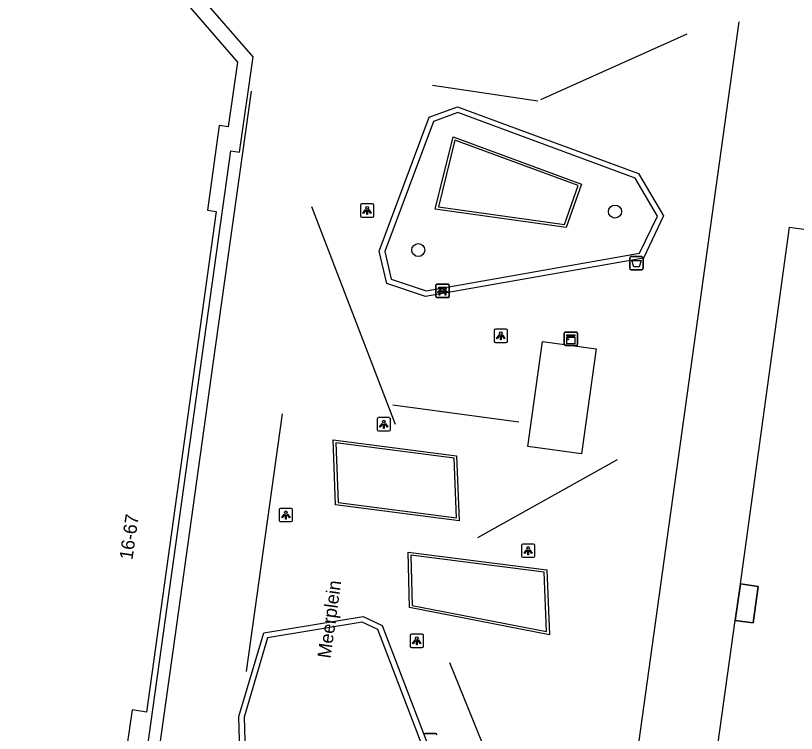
# Model space of a CAD drawing. Extents: x 155640 to 156810, y 382822 to 384046.
# Drawn here: x 156509.5 to 156568, y 383692.6 to 383746.4 of the extents above; entities that cross this region are included whole.
import ezdxf

# ---------------------------------------------------------------- set-up
doc = ezdxf.new("R2010")
doc.units = 0
for name, color, linetype in [('IMGEO_Afvalbak', 7, 'Continuous'), ('IMGEO_Bank', 7, 'Continuous'), ('IMGEO_Boom', 7, 'Continuous'), ('IMGEO_Kast', 7, 'Continuous'), ('IMGEO_Lichtpunt', 7, 'Continuous'), ('IMGEO_Lijnafwatering', 7, 'Continuous'), ('IMGEO_Muur', 7, 'Continuous'), ('IMGEO_Openbare_ruimte_label', 7, 'Continuous'), ('IMGEO_Pand', 7, 'Continuous'), ('IMGEO_Pand_nummerreeks', 7, 'Continuous'), ('IMGEO_Pand_overbouw', 7, 'Continuous'), ('IMGEO_Voetgangersgebied_open', 7, 'Continuous'), ('IMGEO_Voetpad_open', 7, 'Continuous')]:
    doc.layers.add(name, color=color, linetype=linetype)

msp = doc.modelspace()

# ---------------------------------------------------------------- linework, layer by layer
at = {"layer": 'IMGEO_Afvalbak'}
for p, q in [((156555.544, 383727.432), (156555.544, 383728.232)), ((156555.544, 383728.232), (156555.544, 383727.432)), ((156555.644, 383728.332), (156556.434, 383728.332)), ((156556.434, 383728.332), (156555.644, 383728.332)), ((156556.534, 383728.232), (156556.534, 383727.432)), ((156556.534, 383727.432), (156556.534, 383728.232)), ((156556.434, 383727.332), (156555.644, 383727.332)), ((156555.644, 383727.332), (156556.434, 383727.332)), ((156540.197, 383692.575), (156540.987, 383692.575)), ((156540.987, 383692.575), (156540.197, 383692.575))]:
    msp.add_line(p, q, dxfattribs=at)
msp.add_lwpolyline([(156555.687, 383728.046), (156556.391, 383728.046), (156556.242, 383727.576), (156555.836, 383727.576), (156555.687, 383728.046)], dxfattribs=at)
for centre, start, end in [((156555.644, 383728.232), 90, 180), ((156555.644, 383728.232), 90, 180), ((156556.434, 383728.232), 0, 90), ((156556.434, 383728.232), 360, 90), ((156555.644, 383727.432), 180, 270), ((156555.644, 383727.432), 180, 270), ((156556.434, 383727.432), 270, 0), ((156556.434, 383727.432), 270, 0), ((156540.197, 383692.475), 90, 180), ((156540.197, 383692.475), 90, 180), ((156540.987, 383692.475), 0, 90), ((156540.987, 383692.475), 360, 90)]:
    msp.add_arc(centre, 0.1, start, end, dxfattribs=at)
at = {"layer": 'IMGEO_Bank'}
for p, q in [((156541.005, 383725.339), (156541.005, 383726.18)), ((156541.005, 383726.18), (156541.005, 383725.339)), ((156541.08, 383726.264), (156541.921, 383726.264)), ((156541.921, 383726.264), (156541.08, 383726.264)), ((156541.314, 383725.77), (156541.314, 383725.876)), ((156541.358, 383725.876), (156541.358, 383725.77)), ((156541.646, 383725.882), (156541.364, 383725.882)), ((156541.652, 383725.77), (156541.652, 383725.876)), ((156541.696, 383725.876), (156541.696, 383725.77)), ((156542.005, 383726.189), (156542.005, 383725.348)), ((156542.005, 383725.348), (156542.005, 383726.189)), ((156541.93, 383725.264), (156541.089, 383725.264)), ((156541.089, 383725.264), (156541.93, 383725.264)), ((156541.702, 383725.662), (156541.309, 383725.662)), ((156541.364, 383725.764), (156541.646, 383725.764))]:
    msp.add_line(p, q, dxfattribs=at)
for points in [[(156541.308, 383725.882), (156541.222, 383725.882), (156541.222, 383726.043), (156541.785, 383726.043), (156541.785, 383725.882), (156541.702, 383725.882)], [(156541.252, 383725.662), (156541.11, 383725.662), (156541.222, 383725.764), (156541.308, 383725.764)], [(156541.302, 383725.655), (156541.302, 383725.448), (156541.259, 383725.448), (156541.259, 383725.655)], [(156541.702, 383725.764), (156541.785, 383725.764), (156541.897, 383725.662), (156541.758, 383725.662)], [(156541.752, 383725.655), (156541.752, 383725.448), (156541.708, 383725.448), (156541.708, 383725.655)]]:
    msp.add_lwpolyline(points, dxfattribs=at)
for centre, radius, start, end in [((156541.083, 383726.186), 0.0779, 92.4484, 184.28452), ((156541.083, 383726.186), 0.0779, 92.4484, 184.28452), ((156541.307, 383725.875), 0.00671, 2.89567, 87.10433), ((156541.364, 383725.875), 0.00671, 92.89567, 177.10433), ((156541.646, 383725.875), 0.00671, 2.89567, 87.10433), ((156541.703, 383725.875), 0.00671, 92.89567, 177.10433), ((156541.927, 383726.186), 0.0779, 2.4484, 94.28452), ((156541.927, 383726.186), 0.0779, 2.4484, 94.28452), ((156541.083, 383725.342), 0.0779, 182.4484, 274.28452), ((156541.083, 383725.342), 0.0779, 182.4484, 274.28452), ((156541.252, 383725.655), 0.00671, 2.89567, 87.10433), ((156541.309, 383725.655), 0.00671, 92.89567, 177.10433), ((156541.307, 383725.771), 0.00671, 272.89567, 357.10433), ((156541.364, 383725.771), 0.00671, 182.89567, 267.10433), ((156541.646, 383725.771), 0.00671, 272.89567, 357.10433), ((156541.703, 383725.771), 0.00671, 182.89567, 267.10433), ((156541.701, 383725.655), 0.00671, 2.89567, 87.10433), ((156541.758, 383725.655), 0.00671, 92.89567, 177.10433), ((156541.927, 383725.342), 0.0779, 272.4484, 4.28452), ((156541.927, 383725.342), 0.0779, 272.4484, 4.28452)]:
    msp.add_arc(centre, radius, start, end, dxfattribs=at)
at = {"layer": 'IMGEO_Boom'}
for centre in [(156554.432, 383731.713), (156539.683, 383728.825)]:
    msp.add_circle(centre, 0.489, dxfattribs=at)
at = {"layer": 'IMGEO_Kast'}
for p, q in [((156550.631, 383721.746), (156550.631, 383722.587)), ((156550.631, 383722.587), (156550.631, 383721.746)), ((156550.706, 383722.671), (156551.547, 383722.671)), ((156551.547, 383722.671), (156550.706, 383722.671)), ((156551.631, 383722.596), (156551.631, 383721.755)), ((156551.631, 383721.755), (156551.631, 383722.596)), ((156551.556, 383721.671), (156550.715, 383721.671)), ((156550.715, 383721.671), (156551.556, 383721.671))]:
    msp.add_line(p, q, dxfattribs=at)
for points in [[(156550.826, 383722.461), (156551.426, 383722.461), (156551.426, 383722.376), (156550.826, 383722.376), (156550.826, 383722.461)], [(156550.826, 383722.286), (156551.426, 383722.286), (156551.426, 383721.797), (156550.826, 383721.797), (156550.826, 383722.286)]]:
    msp.add_lwpolyline(points, dxfattribs=at)
msp.add_circle((156550.91, 383722.135), 0.0377, dxfattribs=at)
for centre, start, end in [((156550.709, 383722.593), 92.4484, 184.28452), ((156550.709, 383722.593), 92.4484, 184.28452), ((156551.553, 383722.593), 2.4484, 94.28452), ((156551.553, 383722.593), 2.4484, 94.28452), ((156550.709, 383721.749), 182.4484, 274.28452), ((156550.709, 383721.749), 182.4484, 274.28452), ((156551.553, 383721.749), 272.4484, 4.28452), ((156551.553, 383721.749), 272.4484, 4.28452)]:
    msp.add_arc(centre, 0.0779, start, end, dxfattribs=at)
at = {"layer": 'IMGEO_Lichtpunt'}
for p, q in [((156536.245, 383732.286), (156535.437, 383732.286)), ((156536.245, 383732.286), (156535.437, 383732.286)), ((156535.343, 383732.191), (156535.343, 383731.384)), ((156535.343, 383732.191), (156535.343, 383731.384)), ((156536.339, 383731.384), (156536.339, 383732.191)), ((156536.339, 383731.384), (156536.339, 383732.191)), ((156535.437, 383731.29), (156536.245, 383731.29)), ((156535.437, 383731.29), (156536.245, 383731.29)), ((156546.272, 383722.89), (156545.464, 383722.89)), ((156546.272, 383722.89), (156545.464, 383722.89)), ((156545.37, 383722.795), (156545.37, 383721.988)), ((156545.37, 383722.795), (156545.37, 383721.988)), ((156546.366, 383721.988), (156546.366, 383722.795)), ((156546.366, 383721.988), (156546.366, 383722.795)), ((156545.464, 383721.894), (156546.272, 383721.894)), ((156545.464, 383721.894), (156546.272, 383721.894)), ((156536.593, 383716.159), (156536.593, 383715.352)), ((156536.593, 383716.159), (156536.593, 383715.352)), ((156537.495, 383716.254), (156536.687, 383716.254)), ((156537.495, 383716.254), (156536.687, 383716.254)), ((156537.589, 383715.352), (156537.589, 383716.159)), ((156537.589, 383715.352), (156537.589, 383716.159)), ((156536.687, 383715.258), (156537.495, 383715.258)), ((156536.687, 383715.258), (156537.495, 383715.258)), ((156530.156, 383709.452), (156529.348, 383709.452)), ((156530.156, 383709.452), (156529.348, 383709.452)), ((156529.254, 383709.357), (156529.254, 383708.55)), ((156529.254, 383709.357), (156529.254, 383708.55)), ((156530.25, 383708.55), (156530.25, 383709.357)), ((156530.25, 383708.55), (156530.25, 383709.357)), ((156529.348, 383708.456), (156530.156, 383708.456)), ((156529.348, 383708.456), (156530.156, 383708.456)), ((156547.422, 383706.683), (156547.422, 383705.876)), ((156547.422, 383706.683), (156547.422, 383705.876)), ((156548.324, 383706.778), (156547.516, 383706.778)), ((156548.324, 383706.778), (156547.516, 383706.778)), ((156548.418, 383705.876), (156548.418, 383706.683)), ((156548.418, 383705.876), (156548.418, 383706.683)), ((156547.516, 383705.782), (156548.324, 383705.782)), ((156547.516, 383705.782), (156548.324, 383705.782)), ((156539.067, 383699.925), (156539.067, 383699.118)), ((156539.067, 383699.925), (156539.067, 383699.118)), ((156539.969, 383700.02), (156539.161, 383700.02)), ((156539.969, 383700.02), (156539.161, 383700.02)), ((156540.063, 383699.118), (156540.063, 383699.925)), ((156540.063, 383699.118), (156540.063, 383699.925)), ((156539.161, 383699.024), (156539.969, 383699.024)), ((156539.161, 383699.024), (156539.969, 383699.024))]:
    msp.add_line(p, q, dxfattribs=at)
for points in [[(156535.717, 383731.855), (156535.756, 383731.827), (156535.568, 383731.565), (156535.53, 383731.592), (156535.717, 383731.855)], [(156535.819, 383731.807), (156535.866, 383731.807), (156535.866, 383731.485), (156535.819, 383731.485), (156535.819, 383731.807)], [(156535.929, 383731.827), (156535.967, 383731.854), (156536.154, 383731.592), (156536.115, 383731.564), (156535.929, 383731.827)], [(156545.744, 383722.459), (156545.783, 383722.431), (156545.595, 383722.169), (156545.557, 383722.196), (156545.744, 383722.459)], [(156545.846, 383722.411), (156545.893, 383722.411), (156545.893, 383722.089), (156545.846, 383722.089), (156545.846, 383722.411)], [(156545.956, 383722.431), (156545.994, 383722.458), (156546.181, 383722.196), (156546.142, 383722.168), (156545.956, 383722.431)], [(156536.967, 383715.823), (156537.006, 383715.795), (156536.818, 383715.533), (156536.78, 383715.56), (156536.967, 383715.823)], [(156537.069, 383715.775), (156537.116, 383715.775), (156537.116, 383715.453), (156537.069, 383715.453), (156537.069, 383715.775)], [(156537.179, 383715.795), (156537.217, 383715.822), (156537.404, 383715.56), (156537.365, 383715.532), (156537.179, 383715.795)], [(156529.628, 383709.021), (156529.667, 383708.993), (156529.479, 383708.731), (156529.441, 383708.758), (156529.628, 383709.021)], [(156529.73, 383708.973), (156529.777, 383708.973), (156529.777, 383708.651), (156529.73, 383708.651), (156529.73, 383708.973)], [(156529.84, 383708.993), (156529.878, 383709.02), (156530.065, 383708.758), (156530.026, 383708.73), (156529.84, 383708.993)], [(156547.796, 383706.347), (156547.835, 383706.319), (156547.647, 383706.057), (156547.609, 383706.084), (156547.796, 383706.347)], [(156547.898, 383706.299), (156547.945, 383706.299), (156547.945, 383705.977), (156547.898, 383705.977), (156547.898, 383706.299)], [(156548.008, 383706.319), (156548.046, 383706.346), (156548.233, 383706.084), (156548.194, 383706.056), (156548.008, 383706.319)], [(156539.441, 383699.589), (156539.48, 383699.561), (156539.292, 383699.299), (156539.254, 383699.326), (156539.441, 383699.589)], [(156539.543, 383699.541), (156539.59, 383699.541), (156539.59, 383699.219), (156539.543, 383699.219), (156539.543, 383699.541)], [(156539.653, 383699.561), (156539.691, 383699.588), (156539.878, 383699.326), (156539.839, 383699.298), (156539.653, 383699.561)]]:
    msp.add_lwpolyline(points, dxfattribs=at)
for centre in [(156535.842, 383731.989), (156545.869, 383722.593), (156537.092, 383715.957), (156529.753, 383709.155), (156547.921, 383706.481), (156539.566, 383699.723)]:
    msp.add_circle(centre, 0.0994, dxfattribs=at)
for centre, start, end in [((156535.437, 383732.191), 90, 180), ((156535.437, 383732.191), 90, 180), ((156536.245, 383732.191), 0, 90), ((156536.245, 383732.191), 0, 90), ((156535.437, 383731.384), 180, 270), ((156535.437, 383731.384), 180, 270), ((156536.245, 383731.384), 270, 0), ((156536.245, 383731.384), 270, 360), ((156545.464, 383722.795), 90, 180), ((156545.464, 383722.795), 90, 180), ((156546.272, 383722.795), 0, 90), ((156546.272, 383722.795), 0, 90), ((156545.464, 383721.988), 180, 270), ((156545.464, 383721.988), 180, 270), ((156546.272, 383721.988), 270, 0), ((156546.272, 383721.988), 270, 360), ((156536.687, 383716.159), 90, 180), ((156536.687, 383716.159), 90, 180), ((156537.495, 383716.159), 0, 90), ((156537.495, 383716.159), 0, 90), ((156536.687, 383715.352), 180, 270), ((156536.687, 383715.352), 180, 270), ((156537.495, 383715.352), 270, 0), ((156537.495, 383715.352), 270, 360), ((156529.348, 383709.357), 90, 180), ((156529.348, 383709.357), 90, 180), ((156530.156, 383709.357), 0, 90), ((156530.156, 383709.357), 0, 90), ((156529.348, 383708.55), 180, 270), ((156529.348, 383708.55), 180, 270), ((156530.156, 383708.55), 270, 0), ((156530.156, 383708.55), 270, 360), ((156547.516, 383706.683), 90, 180), ((156547.516, 383706.683), 90, 180), ((156548.324, 383706.683), 0, 90), ((156548.324, 383706.683), 0, 90), ((156547.516, 383705.876), 180, 270), ((156547.516, 383705.876), 180, 270), ((156548.324, 383705.876), 270, 0), ((156548.324, 383705.876), 270, 360), ((156539.161, 383699.925), 90, 180), ((156539.161, 383699.925), 90, 180), ((156539.969, 383699.925), 0, 90), ((156539.969, 383699.925), 0, 90), ((156539.161, 383699.118), 180, 270), ((156539.161, 383699.118), 180, 270), ((156539.969, 383699.118), 270, 0), ((156539.969, 383699.118), 270, 360)]:
    msp.add_arc(centre, 0.0946, start, end, dxfattribs=at)
at = {"layer": 'IMGEO_Lijnafwatering'}
for points in [[(156561.191, 383727.612), (156563.741, 383745.941)], [(156548.88, 383740.108), (156559.836, 383745.035)], [(156540.743, 383741.202), (156548.651, 383740.004)], [(156524.313, 383720.285), (156527.182, 383740.744)], [(156537.976, 383715.74), (156531.706, 383732.075)], [(156558.641, 383709.283), (156561.191, 383727.612)], [(156521.445, 383699.826), (156524.313, 383720.285)], [(156537.785, 383717.218), (156547.22, 383715.95)], [(156526.792, 383697.207), (156529.492, 383716.542)], [(156544.141, 383707.275), (156554.615, 383713.117)], [(156556.092, 383690.953), (156558.641, 383709.283)], [(156518.576, 383679.367), (156521.445, 383699.826)], [(156542.023, 383697.887), (156548.413, 383682.123)]]:
    msp.add_lwpolyline(points, dxfattribs=at)
at = {"layer": 'IMGEO_Muur'}
for points in [[(156542.619, 383739.564), (156556.205, 383734.555), (156558.079, 383731.387), (156556.569, 383728.216), (156540.212, 383725.333), (156537.316, 383726.319), (156536.761, 383728.737), (156540.5, 383738.803), (156542.619, 383739.564)], [(156556.272, 383728.58), (156557.629, 383731.374), (156555.934, 383734.214), (156542.65, 383739.13), (156540.811, 383738.477), (156537.178, 383728.704), (156537.66, 383726.629), (156540.265, 383725.766), (156556.272, 383728.58)], [(156550.782, 383730.521), (156540.946, 383731.889), (156542.288, 383737.328), (156551.911, 383733.763), (156550.782, 383730.521)], [(156550.638, 383730.736), (156551.659, 383733.657), (156542.43, 383737.057), (156541.196, 383732.06), (156550.638, 383730.736)], [(156542.554, 383713.385), (156542.745, 383708.518), (156533.486, 383709.704), (156533.288, 383714.598), (156542.554, 383713.385)], [(156542.536, 383708.746), (156542.361, 383713.209), (156533.497, 383714.369), (156533.679, 383709.881), (156542.536, 383708.746)], [(156549.313, 383704.838), (156549.509, 383699.965), (156539.034, 383702.01), (156538.916, 383706.168), (156549.313, 383704.838)], [(156549.12, 383704.661), (156539.123, 383705.94), (156539.229, 383702.175), (156549.299, 383700.209), (156549.12, 383704.661)], [(156540.848, 383690.55), (156540.633, 383688.666), (156533.933, 383679.583), (156526.627, 383679.184), (156526.237, 383693.846), (156528.09, 383700.118), (156535.552, 383701.33), (156536.968, 383700.661), (156540.848, 383690.55)], [(156533.724, 383679.972), (156540.259, 383688.809), (156540.431, 383690.49), (156536.65, 383700.372), (156535.48, 383700.918), (156528.388, 383699.741), (156526.634, 383693.779), (156527.034, 383679.607), (156533.724, 383679.972)]]:
    msp.add_lwpolyline(points, dxfattribs=at)
at = {"layer": 'IMGEO_Pand'}
for points in [[(156504.403, 383768.001), (156526.125, 383742.921), (156525.429, 383738.064), (156524.746, 383738.162), (156523.866, 383731.807), (156524.529, 383731.715), (156519.308, 383694.178), (156518.219, 383694.329), (156517.212, 383687.287), (156518.313, 383687.13), (156516.68, 383675.304), (156436.208, 383686.52), (156438.014, 383699.718), (156438.115, 383699.703), (156438.461, 383700.239)], [(156563.835, 383703.793), (156567.525, 383730.536), (156587.015, 383727.818), (156586.969, 383727.498)], [(156563.835, 383703.793), (156565.167, 383703.586), (156564.787, 383700.857), (156563.438, 383701.044)], [(156554.507, 383636.897), (156554.548, 383637.195), (156563.438, 383701.044)]]:
    msp.add_lwpolyline(points, dxfattribs=at)
at = {"layer": 'IMGEO_Pand_overbouw'}
for points in [[(156518.138, 383682.533), (156525.621, 383736.263), (156526.284, 383736.173), (156527.289, 383743.325), (156522.761, 383748.566), (156522.244, 383748.131), (156489.331, 383786.036)], [(156504.403, 383768.001), (156526.125, 383742.921), (156525.429, 383738.064), (156524.746, 383738.162), (156523.866, 383731.807), (156524.529, 383731.715), (156519.308, 383694.178), (156518.219, 383694.329), (156517.212, 383687.287)]]:
    msp.add_lwpolyline(points, dxfattribs=at)
msp.add_lwpolyline([(156563.438, 383701.044), (156564.787, 383700.857), (156565.167, 383703.586), (156563.835, 383703.793)], close=True, dxfattribs=at)
at = {"layer": 'IMGEO_Voetgangersgebied_open'}
msp.add_lwpolyline([(156553.014, 383721.408), (156551.913, 383713.529), (156547.906, 383714.089), (156549.006, 383721.968), (156553.014, 383721.408)], dxfattribs=at)
at = {"layer": 'IMGEO_Voetpad_open'}
for points in [[(156517.613, 383674.051), (156518.79, 383682.442), (156518.138, 383682.533), (156525.621, 383736.263), (156526.284, 383736.173), (156527.289, 383743.325), (156522.761, 383748.566), (156522.244, 383748.131), (156489.331, 383786.036), (156489.254, 383786.124), (156477.703, 383776.08), (156477.589, 383775.981)], [(156563.438, 383701.044), (156563.835, 383703.793)]]:
    msp.add_lwpolyline(points, dxfattribs=at)

# ---------------------------------------------------------------- texts
at = {"layer": 'IMGEO_Openbare_ruimte_label'}
msp.add_text('Meerplein', height=1, rotation=82.06445, dxfattribs=at).set_placement((156533.102, 383698.162))
at = {"layer": 'IMGEO_Pand_nummerreeks'}
msp.add_text('16-67', height=1, rotation=81.6982, dxfattribs=at).set_placement((156518.246, 383705.55))

doc.saveas('drawing.dxf')
